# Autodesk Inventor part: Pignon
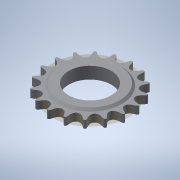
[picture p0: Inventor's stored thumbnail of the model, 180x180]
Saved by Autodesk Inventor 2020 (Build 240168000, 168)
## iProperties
Created: 2008-11
Part Number: Pignon
Document SubType Name: Modeling
Designer: ETUDIANT
Material: Générique
Mass: 24.5854 g
Surface Area: 97.0303 cm^2
Volume: 24.5854 cm^3
Density: 1 g/cm^3
Appearance: Par défaut
Author: ETUDIANT
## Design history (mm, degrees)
sketch "Esquisse1"
  geometry: L1 (-44.316, 0)-(64.157, 0) reference; L2 (0, -46.508)-(0, 92.646) reference; L3 (2.759, 36.646)-(36.422, 30.71); L4 (14.478, 53.426)-(7.14, 11.81); L5 (2.684, 40.658)-(40.913, 33.918); L6 (11.939, 39.026)-(2.821, 34.11); L7 (11.939, 39.026)-(1.847, 36.614); L8 (1.847, 36.614)-(1.619, 37.538); L9 (-1.382, 55.183)-(-5.054, 34.357); L10 (-6.325, 36.288)-(-0.647, 35.287); L11 (6.35, 36.013)-(-4.763, 36.013); L12 (7.105, 39.036)-(4.485, 39.036); L13 (0, 20.2)-(0, 62.827); L14 (-1.847, 36.614)-(-1.619, 37.538); L15 (0, 0)-(-5.654, 32.065); L16 (0, 0)-(5.654, 32.065); C1 r 36.568 at (0, 0); A1 r 4.009 centre (6.35, 36.013) between (2.821, 34.11) and (5.654, 32.065); A2 r 10.377 centre (11.923, 39.094) between (1.847, 36.614) and (2.821, 34.11); A3 r 6.562 centre (-4.763, 36.013) between (1.619, 37.538) and (0.583, 39.818); A4 r 39.823 centre (0, 0) between (0.583, 39.818) and (0, 39.823); A5 r 4.009 centre (-6.35, 36.013) between (-5.654, 32.065) and (-2.821, 34.11); A6 r 10.377 centre (-11.923, 39.094) between (-2.821, 34.11) and (-1.847, 36.614); A7 r 6.562 centre (4.763, 36.013) between (-0.583, 39.818) and (-1.619, 37.538); A8 r 39.823 centre (0, 0) between (0, 39.823) and (-0.583, 39.818); 1 further point
  constraints: 28 end point, 16 point on circle, 9 centre point, 9 point on line, 8 symmetric about line, 5 perpendicular, 3 coincident, 2 tangent, 1 parallel, 4 other
  dimensions: "d0" = 73.13639 diameter of C1; "d3" = 8.01767 diameter of A1; "d5" = 3.9385 distance between parallel lines of L5 L3; "d6" = 10.37669 distance of L6.start L7.end; "d7" = 14.89 deg angle of L7 L6; "d8" = 10.37669 radius of A2 (= d6); "d9" = 0.95208 distance of L7.end L8.end; "d12" = 1.92967 distance between parallel lines of L3 L10; "d14" = 3.02312 distance between parallel lines of L12 L11; "d15" = 6.56172 radius of A3 (derived); "d17" = 39.82264 radius of A4
extrude "Extrusion1" new body sketch "Esquisse1" stored distance "d18" = 7.2; taper "d19" = 0 deg
sketch "Esquisse2"
  geometry: C1 r 30 at (0, 0); C2 r 20 at (0, 0); A1 r 39.823 centre (0, 0) between (14.166, 37.218) and (13.071, 37.616) reference
  constraints: 2 centre point, 2 coincident
  dimensions: "d23" = 40 diameter of C2; "d24" = 60 diameter of C1
extrude "Extrusion2" join sketch "Esquisse2" distance "d25" = 2; taper "d26" = 0 deg
mirror "Miroir1"
extrude "Extrusion3" cut sketch "Esquisse2" extent not by distance; stored distance "d27" = 2; taper "d28" = 0 deg
chamfer "Chanfrein1" distance "d29" = 2; stored, may be unused: second distance "d30" = 2, angle "d31" = 45 deg
sketch "Esquisse3"
  geometry: L1 (-4.482, 25.934)-(4.976, 25.934); L2 (4.976, 25.934)-(4.976, 21.847); L3 (4.976, 21.847)-(-4.482, 21.847); L4 (-4.482, 21.847)-(-4.482, 25.934); L5 (-11.652, -21.154)-(11.006, -21.154); L6 (11.006, -21.154)-(11.006, -24.701); L7 (11.006, -24.701)-(-11.652, -24.701); L8 (-11.652, -24.701)-(-11.652, -21.154)
  constraints: 4 other
feature "Gravure1" sketch "Esquisse3" dims "d32" = 0.1, "d33" = 0
sketch "Esquisse4"
  geometry: C1 r 36 at (0, 0); 1 further point
  constraints: 1 centre point, 1 coincident
  dimensions: "d34" = 72 diameter of C1
feature "SrfExtrusion1" sketch "Esquisse4" dims "d35" = 8, "d36" = 0
node "Solide1"
node "Corps solides"
node "Corps surfaciques"
pattern_circular "Réseau circulaire1" dims angle "d21" = 360 deg
body "Srf1"
other parameters: "d1" = 20 deg, "d2" = 10 deg, "d4" = 4.98104, "d11" = 10.94368, "d16" = 79.64528
